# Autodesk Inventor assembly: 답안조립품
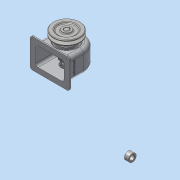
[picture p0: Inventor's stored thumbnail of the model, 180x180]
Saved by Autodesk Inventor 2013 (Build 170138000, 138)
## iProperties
Created: 2016-01
Part Number: 답안조립품
Document SubType Name: Assembly
Designer: Administrator
Author: Administrator
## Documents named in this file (16)
- C:\Users\Administrator\Desktop\460106V1040\답안조립품.iam
- C:\Users\Administrator\Desktop\460106V1040\V-벨트풀리.ipt
- C:\Users\Administrator\Desktop\460106V1040\뒤커버.ipt
- C:\Users\Administrator\Desktop\460106V1040\멈춤나사 - M4x10.ipt
- C:\Users\Administrator\Desktop\460106V1040\베어링 6203.ipt
- C:\Users\Administrator\Desktop\460106V1040\본체.ipt
- C:\Users\Administrator\Desktop\460106V1040\볼트 M3 x 8.ipt
- C:\Users\Administrator\Desktop\460106V1040\볼트 M3 x 10.ipt
- C:\Users\Administrator\Desktop\460106V1040\부시1.ipt
- C:\Users\Administrator\Desktop\460106V1040\부시2.ipt
- C:\Users\Administrator\Desktop\460106V1040\스퍼기어.ipt
- C:\Users\Administrator\Desktop\460106V1040\앞커버.ipt
- C:\Users\Administrator\Desktop\460106V1040\오일씰 28 40 8.ipt
- C:\Users\Administrator\Desktop\460106V1040\축.ipt
- C:\Users\Administrator\Desktop\460106V1040\키 - 5 x 5 x 18.ipt
- C:\Users\Administrator\Desktop\460106V1040\키 - 6 x 6 x 22.ipt
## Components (6 placed, 3 different names)
1. V-벨트풀리:1 — 플러쉬:1
2. ISO 4762 M3 x 8:1
3. ISO 4762 M3 x 10:1
4. ISO 4762 M3 x 8:2
5. ISO 4762 M3 x 8:3
6. ISO 4762 M3 x 8:4
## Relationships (1: Flush 1)
- 플러쉬:1 [Flush]: V-벨트풀리:1
